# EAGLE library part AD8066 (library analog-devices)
High Performance, 145 MHz FastFET Op Amps Source: http://www.analog.com/static/imported-files/data_sheets/AD8065_8066.pdf
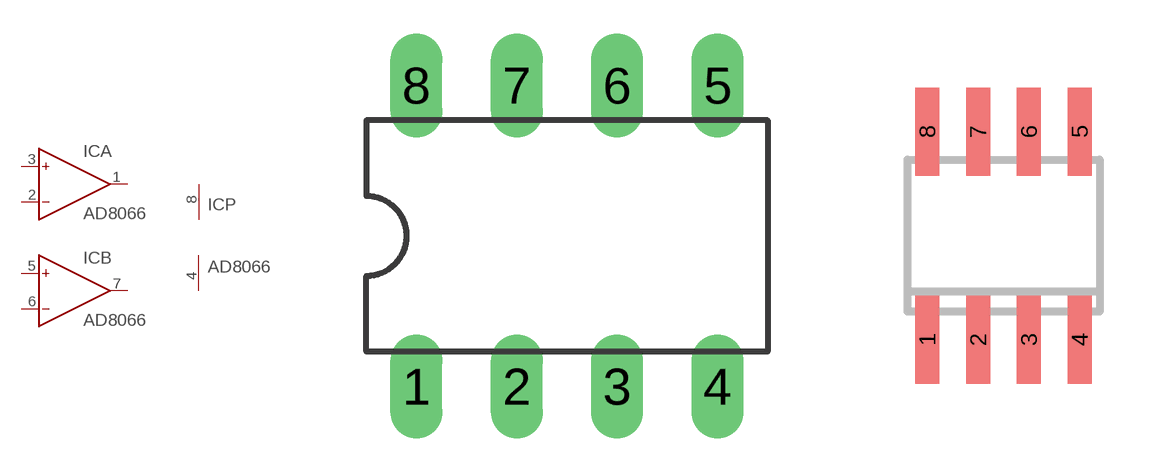
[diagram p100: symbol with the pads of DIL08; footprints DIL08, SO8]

Designator prefix IC; gates A=OP B=OP P=PWR+-

## AD8066N (OC_FARNELL: unknown; OC_NEWARK: unknown)  [DIL08]
1  A:OUT  out
2  A:IN-  in
3  A:IN+  in
4  P:V-  pwr
5  B:IN+  in
6  B:IN-  in
7  B:OUT  out
8  P:V+  pwr

## AD8066R (OC_FARNELL: unknown; OC_NEWARK: unknown)  [SO8]
Pads as for DIL08

## Footprint DIL08 (pad centres in mm)
Dual In Line Package
drill 0.813 long: 1 -3.81,-3.81; 2 -1.27,-3.81; 3 1.27,-3.81; 4 3.81,-3.81; 5 3.81,3.81; 6 1.27,3.81; 7 -1.27,3.81; 8 -3.81,3.81

## Footprint SO8 (pad centres in mm)
8-Lead Small Outline IC (SO-8) Source: http://www.analog.com/UploadedFiles/Data_Sheets/703465986AD8611_2_0.pdf
smd 0.6 x 2.2: 1 -1.905,-2.6; 2 -0.635,-2.6; 3 0.635,-2.6; 4 1.905,-2.6; 5 1.905,2.6; 6 0.635,2.6; 7 -0.635,2.6; 8 -1.905,2.6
